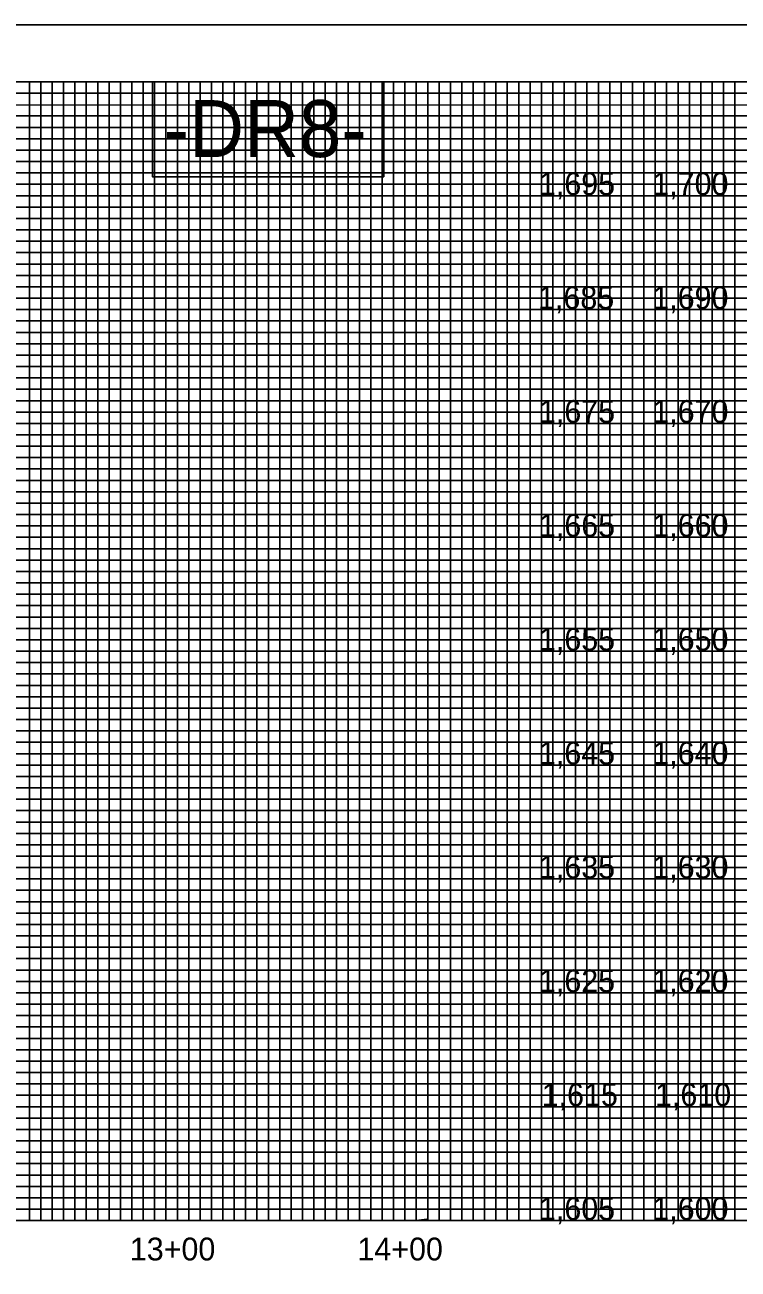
# Model space of a CAD drawing. Extents: x 505602 to 507286, y 483109 to 484209.
# Drawn here: x 506452 to 506765, y 483662 to 484209 of the extents above; entities that cross this region are included whole.
import ezdxf

# ---------------------------------------------------------------- set-up
doc = ezdxf.new("R2010")
doc.units = 0
for name, color, linetype in [('Exist Vertical Profile Vertical Axis Label', 7, 'Continuous'), ('Old_Level_1', 7, 'Continuous'), ('Prop Grid Mask', 7, 'Continuous'), ('Sheet Layout Profile Border Port 2', 7, 'Continuous'), ('Sheet Plot Border Outside CELL', 7, 'Continuous'), ('Sheet Profile CELL', 7, 'Continuous'), ('Sheet Profile Grid Major CELL', 7, 'Continuous'), ('Sheet Profile Grid Middle CELL', 7, 'Continuous'), ('Sheet Profile Grid Minor CELL', 7, 'Continuous')]:
    doc.layers.add(name, color=color, linetype=linetype)

msp = doc.modelspace()

# ---------------------------------------------------------------- linework, layer by layer
at = {"layer": 'Prop Grid Mask'}
msp.add_lwpolyline([(506609.78, 484183.71), (506508.15, 484183.71), (506508.15, 484142), (506609.78, 484142)], close=True, dxfattribs=at)
at = {"layer": 'Sheet Layout Profile Border Port 2'}
msp.add_lwpolyline([(506319.08, 484183.71), (506694.08, 484183.71), (506694.08, 483683.71), (506319.08, 483683.71)], close=True, dxfattribs=at)
at = {"layer": 'Sheet Plot Border Outside CELL'}
msp.add_lwpolyline([(505602.08, 483108.71), (507286.08, 483108.71), (507286.08, 484208.71), (505602.08, 484208.71)], close=True, dxfattribs=at)
at = {"layer": 'Sheet Profile CELL'}
for p, q in [((506719.08, 483683.71), (506719.08, 484183.71)), ((505769.08, 483683.71), (507269.08, 483683.71))]:
    msp.add_line(p, q, dxfattribs=at)
msp.add_lwpolyline([(507269.08, 484183.71), (505769.08, 484183.71), (505769.08, 483133.71), (507269.08, 483133.71)], close=True, dxfattribs=at)
at = {"layer": 'Sheet Profile Grid Major CELL'}
for points in [[(506419.08, 483683.71), (506469.08, 483683.71), (506469.08, 484183.71), (506519.08, 484183.71), (506519.08, 483683.71), (506569.08, 483683.71), (506569.08, 484183.71), (506619.08, 484183.71), (506619.08, 483683.71), (506669.08, 483683.71), (506669.08, 484183.71), (506719.08, 484183.71), (506719.08, 483683.71), (506769.08, 483683.71)], [(505769.08, 484133.71), (507069.08, 484133.71)], [(507069.08, 484083.71), (505769.08, 484083.71), (505769.08, 484033.71), (507069.08, 484033.71)], [(507269.08, 483983.71), (505769.08, 483983.71), (505769.08, 483933.71), (507269.08, 483933.71)], [(507269.08, 483883.71), (505769.08, 483883.71), (505769.08, 483833.71), (507269.08, 483833.71)], [(507269.08, 483783.71), (505769.08, 483783.71), (505769.08, 483783.71), (505769.08, 483733.71), (507269.08, 483733.71)]]:
    msp.add_lwpolyline(points, dxfattribs=at)
at = {"layer": 'Sheet Profile Grid Middle CELL'}
msp.add_line((505769.08, 484158.71), (507069.03, 484158.71), dxfattribs=at)
msp.add_line((505769.08, 484158.71), (507069.03, 484158.71), dxfattribs=at)
for points in [[(506444.08, 483683.71), (506494.08, 483683.71), (506494.08, 484183.71), (506544.08, 484183.71), (506544.08, 483683.71), (506594.08, 483683.71), (506594.08, 484183.71), (506644.08, 484183.71), (506644.08, 483683.71), (506694.08, 483683.71), (506694.08, 484183.71), (506744.08, 484183.71), (506744.08, 483683.71), (506794.08, 483683.71)], [(507069.08, 484108.71), (505769.08, 484108.71), (505769.08, 484058.71), (507069.08, 484058.71)], [(507269.08, 484008.71), (505769.08, 484008.71), (505769.08, 483958.71), (507094.08, 483958.71)], [(507269.08, 483908.71), (505769.08, 483908.71), (505769.08, 483858.71), (507269.08, 483858.71)], [(507269.08, 483808.71), (505769.08, 483808.71), (505769.08, 483758.71), (507269.08, 483758.71)], [(507269.08, 483708.71), (505769.08, 483708.71)]]:
    msp.add_lwpolyline(points, dxfattribs=at)
at = {"layer": 'Sheet Profile Grid Minor CELL'}
for p, q in [((505819.08, 484178.71), (507069.08, 484178.71)), ((507069.08, 484173.71), (505819.08, 484173.36)), ((505819.08, 484168.71), (507069.08, 484168.71)), ((507069.03, 484048.71), (505819.08, 484048.71)), ((507069.08, 484043.71), (505819.08, 484043.71)), ((507069.08, 484038.71), (505819.08, 484038.71)), ((505819.08, 484028.71), (507069.08, 484028.71)), ((507069.08, 484023.71), (505819.08, 484023.71)), ((505819.08, 484018.71), (507219.08, 484018.71)), ((507219.08, 483998.71), (505819.08, 483998.71)), ((505819.08, 483993.71), (507219.08, 483993.71)), ((507219.08, 483973.71), (505819.08, 483973.71)), ((505819.08, 483968.71), (507219.08, 483968.71)), ((507219.08, 483948.71), (505819.08, 483948.71)), ((505819.08, 483943.71), (507219.08, 483943.71)), ((507219.08, 483938.71), (505819.08, 483938.71)), ((505819.08, 483928.71), (507219.08, 483928.71)), ((507219.08, 483923.71), (505819.08, 483923.71)), ((505819.08, 483918.71), (507219.08, 483918.71)), ((507219.08, 483913.71), (505819.08, 483913.71)), ((505819.08, 483903.71), (507219.08, 483903.71)), ((507219.08, 483898.71), (505819.08, 483898.71)), ((505819.08, 483893.71), (507219.08, 483893.71)), ((507219.08, 483888.71), (505819.08, 483888.71)), ((505819.08, 483878.71), (507219.08, 483878.71)), ((507219.08, 483873.71), (505819.08, 483873.71)), ((505819.08, 483868.71), (507219.08, 483868.71)), ((507219.08, 483863.71), (505819.08, 483863.71)), ((505819.08, 483853.71), (507219.08, 483853.71)), ((507219.08, 483848.71), (505819.08, 483848.71)), ((505819.08, 483843.71), (507219.08, 483843.71)), ((507219.08, 483838.71), (505819.08, 483838.71)), ((505819.08, 483828.71), (507219.08, 483828.71)), ((507219.08, 483823.71), (505819.08, 483823.71)), ((505819.08, 483818.71), (507219.08, 483818.71)), ((507219.08, 483813.71), (505819.08, 483813.71)), ((505819.08, 483803.71), (507219.08, 483803.71)), ((507219.08, 483798.71), (505819.08, 483798.71)), ((507219.08, 483793.71), (505819.08, 483793.71)), ((507219.08, 483788.71), (505819.08, 483788.71)), ((505819.08, 483778.71), (507219.08, 483778.71)), ((507219.08, 483773.71), (505819.08, 483773.71)), ((505819.08, 483768.71), (507219.08, 483768.71)), ((507219.08, 483763.71), (505819.08, 483763.71)), ((505819.08, 483753.71), (507219.08, 483753.71)), ((507219.08, 483748.71), (505819.08, 483748.71)), ((505819.08, 483743.71), (507219.08, 483743.71)), ((507219.08, 483738.71), (505819.08, 483738.71)), ((505819.08, 483728.71), (507219.08, 483728.71)), ((507219.08, 483723.71), (505819.08, 483723.71)), ((505819.08, 483718.71), (507219.08, 483718.71)), ((507219.08, 483713.71), (505819.08, 483713.71)), ((505819.08, 483703.71), (507219.08, 483703.71)), ((507219.08, 483698.71), (505819.08, 483698.71)), ((505819.08, 483693.71), (507219.08, 483693.71))]:
    msp.add_line(p, q, dxfattribs=at)
for points in [[(506449.08, 483683.71), (506454.08, 483683.71), (506454.08, 484183.71), (506459.08, 484183.71), (506459.08, 483683.71), (506464.08, 483683.71), (506464.08, 484183.71), (506474.08, 484183.71), (506474.08, 483683.71), (506474.08, 483683.71), (506479.08, 483683.71), (506479.08, 484183.71), (506484.08, 484183.71), (506484.08, 483683.71), (506489.08, 483683.71), (506489.08, 484183.71), (506499.08, 484183.71), (506499.08, 483683.71), (506504.08, 483683.71), (506504.08, 484183.71), (506509.08, 484183.71), (506509.08, 483683.71), (506514.08, 483683.71), (506514.08, 484183.71), (506524.08, 484183.71), (506524.08, 483683.71), (506529.08, 483683.71), (506529.08, 484183.71), (506534.08, 484183.71), (506534.08, 483683.71), (506539.08, 483683.71), (506539.08, 484183.71), (506549.08, 484183.71), (506549.08, 483683.71), (506554.08, 483683.71), (506554.08, 484183.71), (506559.08, 484183.71), (506559.08, 483683.71), (506564.08, 483683.71), (506564.08, 484183.71), (506574.08, 484183.71), (506574.08, 483683.71), (506579.08, 483683.71), (506579.08, 484183.71), (506584.08, 484183.71), (506584.08, 483683.71), (506589.08, 483683.71), (506589.08, 484183.71), (506599.08, 484183.71), (506599.08, 483683.71), (506604.08, 483683.71), (506604.08, 484183.71), (506609.08, 484183.71), (506609.08, 483683.71), (506614.08, 483683.71), (506614.08, 484183.71), (506624.08, 484183.71), (506624.08, 483683.71), (506628.78, 483684.26), (506629.08, 483683.71), (506629.08, 484183.71), (506634.08, 484183.71), (506634.08, 483683.71), (506639.08, 483683.71), (506639.08, 484183.71), (506649.08, 484183.71), (506649.08, 483683.71), (506654.08, 483683.71)], [(506654.08, 483683.71), (506654.08, 484183.71), (506659.08, 484183.71), (506659.08, 483683.71), (506664.08, 483683.71), (506664.08, 484183.71), (506674.08, 484183.71), (506674.08, 483683.71), (506679.08, 483683.71), (506679.08, 484183.71), (506684.08, 484183.71), (506684.08, 483683.71), (506689.08, 483683.71), (506689.08, 484183.71), (506699.08, 484183.71), (506699.08, 483683.71), (506704.08, 483683.71), (506704.08, 484183.71), (506709.08, 484183.71), (506709.08, 483683.71), (506714.08, 483683.71), (506714.08, 484183.71), (506724.08, 484183.71), (506724.08, 483683.71), (506729.08, 483683.71), (506729.08, 484183.71), (506734.08, 484183.71), (506734.08, 483683.71), (506739.08, 483683.71), (506739.08, 484183.71), (506749.08, 484183.71), (506749.08, 483683.71), (506754.08, 483683.71), (506754.08, 484183.71), (506759.08, 484183.71), (506759.08, 483683.71), (506764.08, 483683.71), (506764.08, 484183.71), (506774.08, 484183.71)], [(507069.08, 484163.71), (505819.08, 484163.71), (505819.08, 484153.71), (507069.08, 484153.71)], [(507069.03, 484148.71), (505819.08, 484148.71), (505819.08, 484143.71), (507069.08, 484143.71)], [(507069.08, 484138.71), (505819.08, 484138.71), (505819.08, 484128.71), (507069.08, 484128.71)], [(507069.08, 484123.71), (505819.08, 484123.71), (505819.08, 484118.71), (507069.08, 484118.71)], [(507069.08, 484113.71), (505819.08, 484113.71), (505819.08, 484103.71), (507069.08, 484103.71)], [(507069.08, 484098.71), (505819.08, 484098.71), (505819.08, 484093.71), (507069.08, 484093.71)], [(507069.08, 484088.71), (505819.08, 484088.71), (505819.08, 484078.71), (507069.08, 484078.71)], [(507069.08, 484073.61), (505819.18, 484073.61), (505819.18, 484068.71), (507069.08, 484068.71)], [(507069.08, 484063.71), (505819.08, 484063.71), (505819.08, 484053.71), (507069.08, 484053.71)], [(507219.08, 484013.71), (505819.08, 484013.71), (505819.08, 484003.71), (507219.08, 484003.71)], [(507219.08, 483988.71), (505819.08, 483988.71), (505819.08, 483978.71), (507219.08, 483978.71)], [(507219.08, 483963.71), (505819.08, 483963.71), (505819.08, 483953.71), (507219.08, 483953.71)], [(507219.08, 483688.71), (505819.08, 483688.71)]]:
    msp.add_lwpolyline(points, dxfattribs=at)

# ---------------------------------------------------------------- texts
at = {"layer": 'Exist Vertical Profile Vertical Axis Label'}
for s, p in [('1,695', (506677.98, 484133.96)), ('1,700', (506727.78, 484133.96)), ('1,685', (506677.58, 484083.96)), ('1,690', (506727.78, 484083.96)), ('1,675', (506677.98, 484033.96)), ('1,670', (506727.78, 484033.96)), ('1,665', (506677.98, 483983.96)), ('1,660', (506727.78, 483983.96)), ('1,655', (506677.98, 483933.96)), ('1,650', (506727.78, 483933.96)), ('1,645', (506677.98, 483883.96)), ('1,640', (506727.78, 483883.96)), ('1,635', (506677.98, 483833.96)), ('1,630', (506727.78, 483833.96)), ('1,625', (506677.98, 483783.96)), ('1,620', (506727.78, 483783.96)), ('1,615', (506679.18, 483733.96)), ('1,610', (506728.97, 483733.96)), ('1,605', (506677.98, 483683.96)), ('1,600', (506727.78, 483683.96)), ('13+00', (506498.21, 483666.21)), ('14+00', (506598.21, 483666.21))]:
    msp.add_text(s, height=10, dxfattribs=at).set_placement(p)
at = {"layer": 'Old_Level_1'}
msp.add_text('-DR8-', height=25, dxfattribs=at).set_placement((506513.12, 484150.68))

doc.saveas('drawing.dxf')
